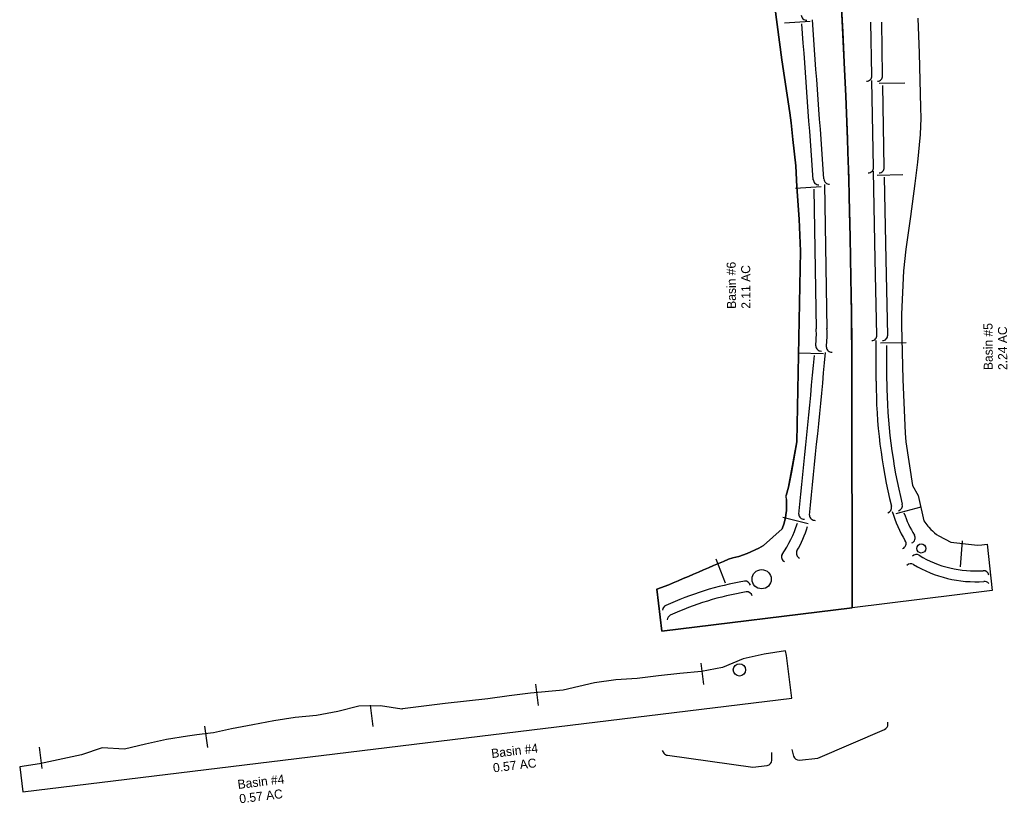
# Model space of a CAD drawing. Extents: x 18433485 to 18438479, y 7649944 to 7654998.
# Drawn here: x 18437561 to 18438479, y 7650111 to 7650839 of the extents above; entities that cross this region are included whole.
import ezdxf

# ---------------------------------------------------------------- set-up
doc = ezdxf.new("R2010")
doc.units = 0
for name, color, linetype in [('DisFills', 7, 'Continuous'), ('DisMisc3', 7, 'Continuous'), ('Intersecting Profile', 7, 'Continuous'), ('TC_Granular', 7, 'Continuous'), ('TL_GroundIntercept', 7, 'Continuous')]:
    doc.layers.add(name, color=color, linetype=linetype)

msp = doc.modelspace()

# ---------------------------------------------------------------- linework, layer by layer
at = {"layer": 'DisFills'}
for centre, radius in [((18438398.54, 7650347.98), 4.23), ((18438250.19, 7650319.39), 8.94), ((18438229.58, 7650235.14), 5.75)]:
    msp.add_circle(centre, radius, dxfattribs=at)
at = {"layer": 'DisMisc3'}
for p, q in [((18438271.5, 7650836.51), (18438295.45, 7650838.09)), ((18438352.68, 7650787.39), (18438351.78, 7650837.03)), ((18438362.68, 7650787.39), (18438361.78, 7650837.03)), ((18438354.24, 7650702.15), (18438352.76, 7650783.05)), ((18438359.4, 7650780.32), (18438383.39, 7650780.7)), ((18438364.24, 7650702.15), (18438362.85, 7650778.37)), ((18438357.47, 7650695.02), (18438381.37, 7650695.42)), ((18438308.6, 7650686.26), (18438310.94, 7650552.14)), ((18438281.65, 7650682.77), (18438305.6, 7650684.35)), ((18438298.67, 7650681.89), (18438300.94, 7650551.97)), ((18438356.59, 7650503.34), (18438356.55, 7650541.32)), ((18438360.56, 7650539.1), (18438384.56, 7650539.53)), ((18438283.7, 7650529.69), (18438307.7, 7650529.14)), ((18438366.59, 7650503.35), (18438366.55, 7650536.55)), ((18438375.37, 7650380.48), (18438398.53, 7650386.73)), ((18438269.98, 7650376.92), (18438293.3, 7650371.25)), ((18438436.69, 7650354.92), (18438434.6, 7650331.02)), ((18438216.63, 7650315.68), (18438207.82, 7650338.01)), ((18438196.56, 7650221.59), (18438194.04, 7650241.43)), ((18438042.8, 7650202.06), (18438040.28, 7650221.9)), ((18437889.03, 7650182.53), (18437886.51, 7650202.37)), ((18437735.27, 7650162.99), (18437732.75, 7650182.83)), ((18438367.48, 7650184.8), (18438367.35, 7650186.46)), ((18438302.34, 7650153.07), (18438364.47, 7650179.82)), ((18437581.5, 7650143.46), (18437578.98, 7650163.3)), ((18438157.62, 7650160.07), (18438159.29, 7650157.76)), ((18438162.64, 7650155.74), (18438242.08, 7650144.56)), ((18438259.74, 7650151.29), (18438259.69, 7650158.36)), ((18438278.19, 7650161.26), (18438279.96, 7650154.98)), ((18438242.08, 7650144.56), (18438255.39, 7650146.3)), ((18438285.27, 7650151.36), (18438302.34, 7650153.07))]:
    msp.add_line(p, q, dxfattribs=at)
for points in [[(18438357.4, 7650546.25), (18438355.81, 7650616.4), (18438354.31, 7650698.7)], [(18438367.4, 7650546.25), (18438365.81, 7650616.4), (18438364.41, 7650693.14)]]:
    msp.add_lwpolyline(points, dxfattribs=at)
for centre, radius, start, end in [((18438292, 7650843.99), 5, 182.55462, 272.99421), ((18305142.26, 7641087.71), 133501.69, 4.12492, 4.1872772), ((18305142.26, 7641087.71), 133511.69, 4.12492, 4.1885569), ((18438347.69, 7650787.29), 5, 270.91394, 1.048), ((18438357.69, 7650787.29), 5, 270.91394, 1.048), ((18438349.24, 7650702.05), 5, 270.95747, 1.048), ((18438359.24, 7650702.05), 5, 270.95747, 1.048), ((18438303.11, 7650691.01), 5, 182.55462, 272.99421), ((18438313.09, 7650691.6), 5, 182.55462, 272.99421), ((18438209.83, 7650546.89), 91.25, 353.30945, 3.191), ((18438209.83, 7650546.89), 101.25, 353.30945, 3.191), ((18438352.41, 7650546.13), 5, 271.02714, 1.29954), ((18438362.41, 7650546.13), 5, 271.02714, 1.29954), ((18419563.96, 7652319.6), 18830.92, 354.084453, 354.546872), ((18438305.45, 7650536.48), 5, 182.55462, 272.99421), ((18438315.39, 7650535.31), 5, 182.55462, 272.99421), ((18419563.96, 7652319.6), 18820.92, 354.084453, 354.535583), ((18438839.65, 7650503.87), 483.06, 180.06268, 193.98212), ((18438849.65, 7650505.84), 483.06, 180.30201, 193.98212), ((18438366.05, 7650385.94), 5, 285.09027, 13.98212), ((18438376.05, 7650387.92), 5, 285.09027, 13.98212), ((18438289.66, 7650380.1), 5, 182.55462, 272.99421), ((18438299.6, 7650379.07), 5, 182.55462, 272.99421), ((18438481.33, 7650414.95), 114.46, 196.5229, 211.49121), ((18438481.33, 7650414.95), 104.46, 198.89384, 211.49121), ((18438179.86, 7650404.38), 108.7, 325.21719, 342.33022), ((18438179.86, 7650404.38), 118.7, 330.34654, 342.33022), ((18438379.46, 7650352.55), 5, 290.90835, 31.49121), ((18438387.99, 7650357.77), 5, 290.90835, 31.49121), ((18438273.65, 7650340.21), 5, 154.39014, 244.82973), ((18438287.52, 7650343.49), 5, 154.39014, 244.82973), ((18438394.04, 7650337.38), 5, 58.87296, 136.44582), ((18438448.75, 7650427.3), 100.26, 238.68223, 274.20214), ((18438388.86, 7650328.82), 5, 58.87296, 136.44582), ((18438448.75, 7650427.3), 110.26, 238.68223, 274.20214), ((18438456.47, 7650322.32), 5, 10.49128, 94.20214), ((18438282.11, 7650032.12), 289.35, 99.54531, 114.73356), ((18438234.96, 7650312.54), 5, 13.79484, 99.54531), ((18438457.2, 7650312.35), 5, 36.08546, 94.20214), ((18438282.11, 7650032.12), 279.35, 99.54531, 114.73356), ((18438236.62, 7650302.68), 5, 13.79484, 99.54531), ((18438163.14, 7650290.39), 5, 114.73356, 175.78195), ((18438167.32, 7650281.31), 5, 114.73356, 175.78195), ((18438362.49, 7650184.41), 5, 293.29299, 4.40437), ((18438163.34, 7650160.69), 5, 215.85939, 261.98993), ((18438284.77, 7650156.33), 5, 195.6982, 275.72971), ((18438254.74, 7650151.26), 5, 277.44969, 0.35739)]:
    msp.add_arc(centre, radius, start, end, dxfattribs=at)
at = {"layer": 'Intersecting Profile'}
msp.add_lwpolyline([(18437563.42, 7650121.72), (18438278.14, 7650208.8), (18438273.32, 7650248.36), (18438272.44, 7650252.84), (18438252.66, 7650249.83), (18438233.06, 7650245.29), (18438213.87, 7650237.43), (18438194.18, 7650233.72), (18438174.25, 7650231.85), (18438154.4, 7650229.48), (18438134.52, 7650227.22), (18438114.54, 7650225.86), (18438094.73, 7650223.07), (18438065.71, 7650216.34), (18438035.46, 7650213.46), (18438015.62, 7650210.92), (18437995.8, 7650208.25), (18437975.92, 7650206.03), (18437956.04, 7650203.83), (18437936.18, 7650201.45), (18437916.35, 7650198.84), (18437915.63, 7650198.73), (18437895.86, 7650201.67), (18437875.75, 7650201.39), (18437856.22, 7650196.3), (18437836.5, 7650192.78), (18437816.59, 7650190.86), (18437796.81, 7650187.78), (18437777.1, 7650184.18), (18437757.41, 7650180.43), (18437740.64, 7650176.61), (18437737.77, 7650176.26), (18437725.19, 7650174.84), (18437716.59, 7650173.6), (18437696.86, 7650170.3), (18437677.33, 7650165.95), (18437657.81, 7650161.56), (18437637.21, 7650162.79), (18437618.12, 7650156.15), (18437579.01, 7650147.7), (18437560.59, 7650145)], close=True, dxfattribs=at)
at = {"layer": 'TC_Granular'}
msp.add_lwpolyline([(18438395.5, 7650840.87), (18438396.78, 7650808.27), (18438397.85, 7650757.73), (18438398.12, 7650748.03), (18438397.42, 7650732.65), (18438395.02, 7650707.08), (18438392.69, 7650687.11), (18438388.42, 7650656.41), (18438386.31, 7650641.34), (18438384.2, 7650626.27), (18438381.96, 7650605.86), (18438381.06, 7650585.75), (18438380.15, 7650565.64), (18438380.25, 7650560.56), (18438380.35, 7650555.47), (18438380.95, 7650530.3), (18438381.54, 7650505.12), (18438383.65, 7650455.12), (18438384.23, 7650447.12), (18438390.37, 7650406.35), (18438395.77, 7650397.14), (18438401.03, 7650373.76), (18438404.66, 7650368.73), (18438405.46, 7650367.78), (18438407.54, 7650365.59), (18438408.96, 7650364.23), (18438410.86, 7650362.61), (18438412.86, 7650361.1), (18438414.94, 7650359.71), (18438426.2, 7650353.93), (18438450.96, 7650351.01), (18438454.97, 7650351.48), (18438459.96, 7650351.81), (18438464.57, 7650308.82), (18438334.34, 7650292.77), (18438334.05, 7650505.05), (18438334.02, 7650517.26), (18438333.97, 7650530.11), (18438333.81, 7650553), (18438333.68, 7650566.47), (18438333.49, 7650582.51), (18438333.29, 7650596.38), (18438333.11, 7650607.18), (18438332.89, 7650619.53), (18438332.41, 7650642.47), (18438332.02, 7650659.14), (18438331.53, 7650677.39), (18438331.18, 7650689.75), (18438330.23, 7650719.39), (18438329.33, 7650744.17), (18438328, 7650776.88), (18438326.96, 7650799.96), (18438325.39, 7650831.79), (18438324.36, 7650851.18)], dxfattribs=at)
at = {"layer": 'TL_GroundIntercept'}
for p, q in [((18438325.58, 7650828.07), (18438323.49, 7650866.72)), ((18438262.57, 7650851.47), (18438269.11, 7650802.2)), ((18438326.97, 7650799.66), (18438325.58, 7650828.07)), ((18438269.11, 7650802.2), (18438276.52, 7650752.9)), ((18438328.36, 7650768.47), (18438326.97, 7650799.66)), ((18438329.9, 7650728.81), (18438328.36, 7650768.47)), ((18438276.52, 7650752.9), (18438277.62, 7650743.41)), ((18438277.62, 7650743.41), (18438279.25, 7650728.18)), ((18438279.25, 7650728.18), (18438281.91, 7650703.45)), ((18438330.33, 7650716.35), (18438329.9, 7650728.81)), ((18438331.11, 7650692.04), (18438330.33, 7650716.35)), ((18438281.91, 7650703.45), (18438283, 7650683.92)), ((18438331.61, 7650674.68), (18438331.11, 7650692.04)), ((18438283, 7650683.92), (18438285.01, 7650653.89)), ((18438331.93, 7650662.52), (18438331.61, 7650674.68)), ((18438332.53, 7650637.09), (18438331.93, 7650662.52)), ((18438285.01, 7650653.89), (18438286.37, 7650624.32)), ((18438332.91, 7650618.36), (18438332.53, 7650637.09)), ((18438286.37, 7650624.32), (18438282.98, 7650446.98)), ((18438333.24, 7650599.15), (18438332.91, 7650618.36)), ((18438333.66, 7650568.14), (18438333.24, 7650599.15)), ((18438333.93, 7650537.59), (18438333.66, 7650568.14)), ((18438334.05, 7650505.05), (18438333.93, 7650537.59)), ((18438334.34, 7650292.77), (18438334.05, 7650505.05)), ((18438282.98, 7650446.98), (18438277.85, 7650418.88)), ((18438277.85, 7650418.88), (18438275.32, 7650404.97)), ((18438275.32, 7650404.97), (18438273.08, 7650397.12)), ((18438273.1, 7650396.27), (18438273.08, 7650397.12)), ((18438273.19, 7650393.5), (18438273.1, 7650396.27)), ((18438273.19, 7650393.5), (18438273.26, 7650391.27)), ((18438273.23, 7650383.13), (18438272.81, 7650379.16)), ((18438273.32, 7650384.46), (18438273.23, 7650383.13)), ((18438273.26, 7650391.27), (18438273.37, 7650388.09)), ((18438273.38, 7650387.06), (18438273.32, 7650384.46)), ((18438273.37, 7650388.09), (18438273.38, 7650387.06)), ((18438271.83, 7650374.32), (18438271.01, 7650371.36)), ((18438272.35, 7650376.56), (18438271.83, 7650374.32)), ((18438272.81, 7650379.16), (18438272.35, 7650376.56)), ((18438269.14, 7650366.34), (18438251.91, 7650350.69)), ((18438271.01, 7650371.36), (18438269.14, 7650366.34)), ((18438247.66, 7650348.24), (18438236.72, 7650343.34)), ((18438251.91, 7650350.69), (18438247.66, 7650348.24)), ((18438219.47, 7650337.96), (18438214.79, 7650335.99)), ((18438223.56, 7650339.27), (18438219.47, 7650337.96)), ((18438229.13, 7650340.56), (18438223.56, 7650339.27)), ((18438236.72, 7650343.34), (18438229.13, 7650340.56)), ((18438196.07, 7650328.06), (18438191.4, 7650326.04)), ((18438200.74, 7650330.06), (18438196.07, 7650328.06)), ((18438205.42, 7650332.04), (18438200.74, 7650330.06)), ((18438210.1, 7650334.02), (18438205.42, 7650332.04)), ((18438214.79, 7650335.99), (18438210.1, 7650334.02)), ((18438177.39, 7650319.95), (18438172.7, 7650318)), ((18438182.06, 7650321.96), (18438177.39, 7650319.95)), ((18438186.73, 7650324), (18438182.06, 7650321.96)), ((18438191.4, 7650326.04), (18438186.73, 7650324)), ((18438163.96, 7650314.23), (18438152.87, 7650310.22)), ((18438152.87, 7650310.22), (18438157.51, 7650270.99)), ((18438168.01, 7650316.08), (18438163.96, 7650314.23)), ((18438172.7, 7650318), (18438168.01, 7650316.08)), ((18438157.51, 7650270.99), (18438334.34, 7650292.77))]:
    msp.add_line(p, q, dxfattribs=at)
msp.add_lwpolyline([(18438323.49, 7650866.72), (18438325.58, 7650828.07), (18438326.97, 7650799.66), (18438328.36, 7650768.47), (18438329.9, 7650728.81), (18438330.33, 7650716.35), (18438331.11, 7650692.04), (18438331.61, 7650674.68), (18438331.93, 7650662.52), (18438332.53, 7650637.09), (18438332.91, 7650618.36), (18438333.24, 7650599.15), (18438333.66, 7650568.14), (18438333.93, 7650537.59), (18438334.05, 7650505.05), (18438334.34, 7650292.77), (18438157.51, 7650270.99), (18438152.87, 7650310.22), (18438163.96, 7650314.23), (18438168.01, 7650316.08), (18438172.7, 7650318), (18438177.39, 7650319.95), (18438182.06, 7650321.96), (18438186.73, 7650324), (18438191.4, 7650326.04), (18438196.07, 7650328.06), (18438200.74, 7650330.06), (18438205.42, 7650332.04), (18438210.1, 7650334.02), (18438214.79, 7650335.99), (18438219.47, 7650337.96), (18438223.56, 7650339.27), (18438229.13, 7650340.56), (18438236.72, 7650343.34), (18438247.66, 7650348.24), (18438251.91, 7650350.69), (18438269.14, 7650366.34), (18438271.01, 7650371.36), (18438271.83, 7650374.32), (18438272.35, 7650376.56), (18438272.81, 7650379.16), (18438273.23, 7650383.13), (18438273.32, 7650384.46), (18438273.38, 7650387.06), (18438273.37, 7650388.09), (18438273.26, 7650391.27), (18438273.19, 7650393.5), (18438273.08, 7650397.12), (18438275.32, 7650404.97), (18438282.98, 7650446.98), (18438286.37, 7650624.32), (18438285.01, 7650653.89), (18438283, 7650683.92), (18438281.91, 7650703.45), (18438279.25, 7650728.18), (18438277.62, 7650743.41), (18438276.52, 7650752.9), (18438269.11, 7650802.2), (18438262.57, 7650851.47)], dxfattribs=at)

# ---------------------------------------------------------------- texts
at = {"layer": 'Intersecting Profile'}
for s, p in [('Basin #4', (18437999.39, 7650153.15)), ('0.57 AC', (18438001.02, 7650139.81)), ('Basin #4', (18437763.59, 7650124.42)), ('0.57 AC', (18437765.22, 7650111.08))]:
    msp.add_text(s, height=8.4, rotation=6.94701, dxfattribs=at).set_placement(p)
at = {"layer": 'TC_Granular'}
for s, p in [('Basin #5', (18438465.07, 7650513.74)), ('2.24 AC', (18438478.51, 7650513.83))]:
    msp.add_text(s, height=8.4, rotation=90.37147, dxfattribs=at).set_placement(p)
at = {"layer": 'TL_GroundIntercept'}
for s, p in [('Basin #6', (18438226.4, 7650570.7)), ('2.11 AC', (18438239.84, 7650570.8))]:
    msp.add_text(s, height=8.4, rotation=90.45093, dxfattribs=at).set_placement(p)

doc.saveas('drawing.dxf')
